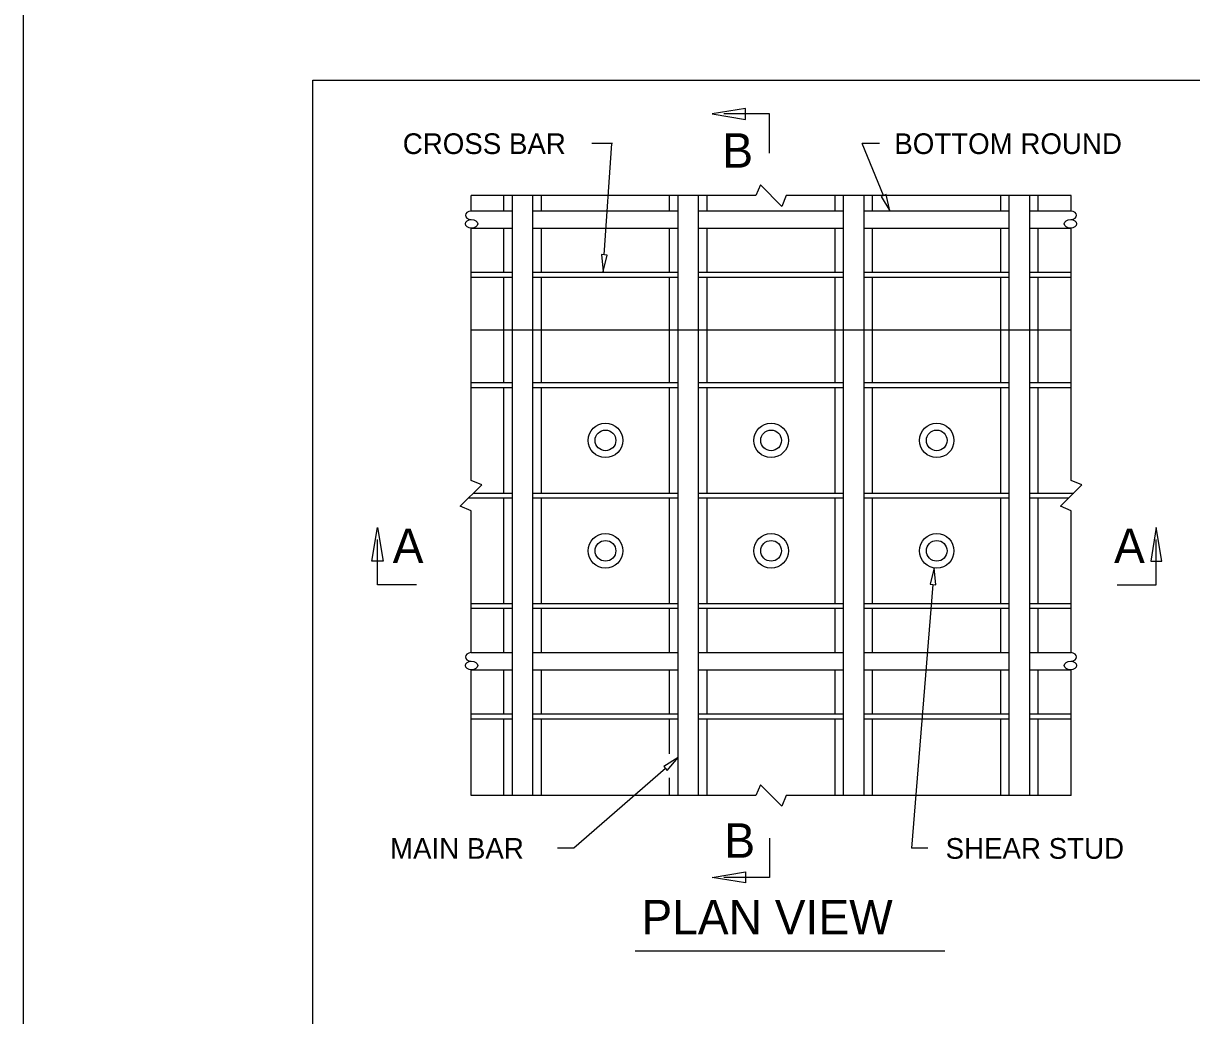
# Model space of a CAD drawing. Extents: x -24512 to -22484, y 4569 to 6351.
# Drawn here: x -24179.8 to -24010.5, y 5605 to 5748.8 of the extents above; entities that cross this region are included whole.
import ezdxf

# ---------------------------------------------------------------- set-up
doc = ezdxf.new("R2010")
doc.units = 0
for name, color, linetype in [('10', 7, 'Continuous'), ('2', 7, 'Continuous'), ('3', 7, 'Continuous'), ('4', 7, 'Continuous'), ('6', 7, 'Continuous'), ('9', 7, 'Continuous'), ('PLT-BNDY', 7, 'Continuous')]:
    doc.layers.add(name, color=color, linetype=linetype)

msp = doc.modelspace()

# ---------------------------------------------------------------- linework, layer by layer
at = {"layer": '10'}
msp.add_line((-24046.26, 5614.39), (-24091.12, 5614.39), dxfattribs=at)
for centre, major_axis, start_param, end_param in [((-24114.81, 5721.02), (0.895, 0), 1.692197, 4.591233), ((-24028.04, 5721.02), (-0.895, 0), 1.691952, 4.590988), ((-24114.81, 5657.02), (0.895, 0), 1.692197, 4.591233), ((-24028.04, 5657.02), (-0.895, 0), 1.691952, 4.590988)]:
    msp.add_ellipse(centre, major_axis=major_axis, ratio=0.699516, start_param=start_param, end_param=end_param, dxfattribs=at)
for centre, major_axis in [((-24114.81, 5719.77), (0.895, 0)), ((-24028.04, 5719.77), (-0.895, 0)), ((-24114.81, 5655.77), (0.895, 0)), ((-24028.04, 5655.77), (-0.895, 0))]:
    msp.add_ellipse(centre, major_axis=major_axis, ratio=0.699516, dxfattribs=at)
at = {"layer": '2'}
for p, q in [((-24137.79, 5740.63), (-23353.75, 5740.63)), ((-24137.79, 5178.04), (-24137.79, 5740.63))]:
    msp.add_line(p, q, dxfattribs=at)
at = {"layer": '3'}
for points in [[(-24075.12, 5734.9), (-24075.12, 5736.52), (-24079.97, 5735.71)], [(-24127.64, 5670.92), (-24129.26, 5670.92), (-24128.45, 5675.77)], [(-24016.41, 5670.92), (-24014.79, 5670.92), (-24015.6, 5675.77)], [(-24075.12, 5625.89), (-24075.12, 5624.27), (-24079.97, 5625.08)]]:
    msp.add_lwpolyline(points, close=True, dxfattribs=at)
for points in [[(-24071.65, 5730.05), (-24071.65, 5735.71), (-24078.25, 5735.71)], [(-24122.79, 5667.45), (-24128.45, 5667.45), (-24128.45, 5674.04)], [(-24021.26, 5667.45), (-24015.6, 5667.45), (-24015.6, 5674.04)], [(-24071.65, 5630.74), (-24071.65, 5625.08), (-24078.25, 5625.08)]]:
    msp.add_lwpolyline(points, dxfattribs=at)
at = {"layer": '4'}
for p, q in [((-24114.88, 5721.65), (-24114.88, 5723.87)), ((-24110.13, 5721.65), (-24110.13, 5723.87)), ((-24108.9, 5636.93), (-24108.9, 5723.87)), ((-24105.93, 5636.93), (-24105.93, 5723.87)), ((-24104.69, 5721.65), (-24104.69, 5723.87)), ((-24086.13, 5721.65), (-24086.13, 5723.87)), ((-24084.9, 5636.93), (-24084.9, 5723.87)), ((-24081.93, 5636.93), (-24081.93, 5723.87)), ((-24080.69, 5721.65), (-24080.69, 5723.87)), ((-24062.13, 5721.65), (-24062.13, 5723.87)), ((-24060.9, 5636.93), (-24060.9, 5723.87)), ((-24057.93, 5636.93), (-24057.93, 5723.87)), ((-24056.7, 5721.65), (-24056.7, 5723.87)), ((-24038.13, 5721.65), (-24038.13, 5723.87)), ((-24036.9, 5636.93), (-24036.9, 5723.87)), ((-24033.93, 5636.93), (-24033.93, 5723.87)), ((-24032.7, 5721.65), (-24032.7, 5723.87)), ((-24027.94, 5721.65), (-24027.94, 5723.87)), ((-24114.88, 5721.65), (-24108.9, 5721.65)), ((-24105.93, 5721.65), (-24084.9, 5721.65)), ((-24081.93, 5721.65), (-24060.9, 5721.65)), ((-24057.93, 5721.65), (-24036.9, 5721.65)), ((-24033.93, 5721.65), (-24027.94, 5721.65)), ((-24114.88, 5719.15), (-24108.9, 5719.15)), ((-24110.13, 5712.77), (-24110.13, 5719.15)), ((-24105.93, 5719.15), (-24084.9, 5719.15)), ((-24104.69, 5712.77), (-24104.69, 5719.15)), ((-24086.13, 5712.77), (-24086.13, 5719.15)), ((-24081.93, 5719.15), (-24060.9, 5719.15)), ((-24080.69, 5712.77), (-24080.69, 5719.15)), ((-24062.13, 5712.77), (-24062.13, 5719.15)), ((-24057.93, 5719.15), (-24036.9, 5719.15)), ((-24056.7, 5712.77), (-24056.7, 5719.15)), ((-24038.13, 5712.77), (-24038.13, 5719.15)), ((-24033.93, 5719.15), (-24027.94, 5719.15)), ((-24032.7, 5712.77), (-24032.7, 5719.15)), ((-24114.88, 5712.77), (-24108.9, 5712.77)), ((-24108.9, 5712.02), (-24114.88, 5712.02)), ((-24110.13, 5696.77), (-24110.13, 5712.02)), ((-24105.93, 5712.77), (-24084.9, 5712.77)), ((-24084.9, 5712.02), (-24105.93, 5712.02)), ((-24104.69, 5696.77), (-24104.69, 5712.02)), ((-24086.13, 5696.77), (-24086.13, 5712.02)), ((-24081.93, 5712.77), (-24060.9, 5712.77)), ((-24060.9, 5712.02), (-24081.93, 5712.02)), ((-24080.69, 5696.77), (-24080.69, 5712.02)), ((-24062.13, 5696.77), (-24062.13, 5712.02)), ((-24057.93, 5712.77), (-24036.9, 5712.77)), ((-24036.9, 5712.02), (-24057.93, 5712.02)), ((-24056.7, 5696.77), (-24056.7, 5712.02)), ((-24038.13, 5696.77), (-24038.13, 5712.02)), ((-24033.93, 5712.77), (-24027.94, 5712.77)), ((-24027.94, 5712.02), (-24033.93, 5712.02)), ((-24032.7, 5696.77), (-24032.7, 5712.02)), ((-24114.88, 5696.77), (-24108.9, 5696.77)), ((-24105.93, 5696.77), (-24084.9, 5696.77)), ((-24081.93, 5696.77), (-24060.9, 5696.77)), ((-24057.93, 5696.77), (-24036.9, 5696.77)), ((-24033.93, 5696.77), (-24027.94, 5696.77)), ((-24108.9, 5696.02), (-24114.88, 5696.02)), ((-24110.13, 5680.77), (-24110.13, 5696.02)), ((-24084.9, 5696.02), (-24105.93, 5696.02)), ((-24104.69, 5680.77), (-24104.69, 5696.02)), ((-24086.13, 5680.77), (-24086.13, 5696.02)), ((-24060.9, 5696.02), (-24081.93, 5696.02)), ((-24080.69, 5680.77), (-24080.69, 5696.02)), ((-24062.13, 5680.77), (-24062.13, 5696.02)), ((-24036.9, 5696.02), (-24057.93, 5696.02)), ((-24056.7, 5680.77), (-24056.7, 5696.02)), ((-24038.13, 5680.77), (-24038.13, 5696.02)), ((-24027.94, 5696.02), (-24033.93, 5696.02)), ((-24032.7, 5680.77), (-24032.7, 5696.02)), ((-24108.9, 5680.02), (-24115.26, 5680.02)), ((-24114.51, 5680.77), (-24108.9, 5680.77)), ((-24110.13, 5664.77), (-24110.13, 5680.02)), ((-24105.93, 5680.77), (-24084.9, 5680.77)), ((-24084.9, 5680.02), (-24105.93, 5680.02)), ((-24104.69, 5664.77), (-24104.69, 5680.02)), ((-24086.13, 5664.77), (-24086.13, 5680.02)), ((-24081.93, 5680.77), (-24060.9, 5680.77)), ((-24060.9, 5680.02), (-24081.93, 5680.02)), ((-24080.69, 5664.77), (-24080.69, 5680.02)), ((-24062.13, 5664.77), (-24062.13, 5680.02)), ((-24057.93, 5680.77), (-24036.9, 5680.77)), ((-24036.9, 5680.02), (-24057.93, 5680.02)), ((-24056.7, 5664.77), (-24056.7, 5680.02)), ((-24038.13, 5664.77), (-24038.13, 5680.02)), ((-24033.93, 5680.77), (-24027.57, 5680.77)), ((-24028.32, 5680.02), (-24033.93, 5680.02)), ((-24032.7, 5664.77), (-24032.7, 5680.02)), ((-24114.88, 5664.77), (-24108.9, 5664.77)), ((-24108.9, 5664.02), (-24114.88, 5664.02)), ((-24110.13, 5657.65), (-24110.13, 5664.02)), ((-24105.93, 5664.77), (-24084.9, 5664.77)), ((-24084.9, 5664.02), (-24105.93, 5664.02)), ((-24104.69, 5657.65), (-24104.69, 5664.02)), ((-24086.13, 5657.65), (-24086.13, 5664.02)), ((-24081.93, 5664.77), (-24060.9, 5664.77)), ((-24060.9, 5664.02), (-24081.93, 5664.02)), ((-24080.69, 5657.65), (-24080.69, 5664.02)), ((-24062.13, 5657.65), (-24062.13, 5664.02)), ((-24057.93, 5664.77), (-24036.9, 5664.77)), ((-24036.9, 5664.02), (-24057.93, 5664.02)), ((-24056.7, 5657.65), (-24056.7, 5664.02)), ((-24038.13, 5657.65), (-24038.13, 5664.02)), ((-24033.93, 5664.77), (-24027.94, 5664.77)), ((-24027.94, 5664.02), (-24033.93, 5664.02)), ((-24032.7, 5657.65), (-24032.7, 5664.02)), ((-24114.88, 5657.65), (-24108.9, 5657.65)), ((-24105.93, 5657.65), (-24084.9, 5657.65)), ((-24081.93, 5657.65), (-24060.9, 5657.65)), ((-24057.93, 5657.65), (-24036.9, 5657.65)), ((-24033.93, 5657.65), (-24027.94, 5657.65)), ((-24114.88, 5655.15), (-24108.9, 5655.15)), ((-24114.88, 5636.93), (-24114.88, 5655.15)), ((-24110.13, 5648.77), (-24110.13, 5655.15)), ((-24105.93, 5655.15), (-24084.9, 5655.15)), ((-24104.69, 5648.77), (-24104.69, 5655.15)), ((-24086.13, 5648.77), (-24086.13, 5655.15)), ((-24081.93, 5655.15), (-24060.9, 5655.15)), ((-24080.69, 5648.77), (-24080.69, 5655.15)), ((-24062.13, 5648.77), (-24062.13, 5655.15)), ((-24057.93, 5655.15), (-24036.9, 5655.15)), ((-24056.7, 5648.77), (-24056.7, 5655.15)), ((-24038.13, 5648.77), (-24038.13, 5655.15)), ((-24033.93, 5655.15), (-24027.94, 5655.15)), ((-24032.7, 5648.77), (-24032.7, 5655.15)), ((-24027.94, 5636.93), (-24027.94, 5655.15)), ((-24114.88, 5648.77), (-24108.9, 5648.77)), ((-24105.93, 5648.77), (-24084.9, 5648.77)), ((-24081.93, 5648.77), (-24060.9, 5648.77)), ((-24057.93, 5648.77), (-24036.9, 5648.77)), ((-24033.93, 5648.77), (-24027.94, 5648.77)), ((-24108.9, 5648.02), (-24114.88, 5648.02)), ((-24110.13, 5636.93), (-24110.13, 5648.02)), ((-24084.9, 5648.02), (-24105.93, 5648.02)), ((-24104.69, 5636.93), (-24104.69, 5648.02)), ((-24086.13, 5642.99), (-24086.13, 5648.02)), ((-24060.9, 5648.02), (-24081.93, 5648.02)), ((-24080.69, 5636.93), (-24080.69, 5648.02)), ((-24062.13, 5636.93), (-24062.13, 5648.02)), ((-24036.9, 5648.02), (-24057.93, 5648.02)), ((-24056.7, 5636.93), (-24056.7, 5648.02)), ((-24038.13, 5636.93), (-24038.13, 5648.02)), ((-24027.94, 5648.02), (-24033.93, 5648.02)), ((-24032.7, 5636.93), (-24032.7, 5648.02)), ((-24086.13, 5636.93), (-24086.13, 5639.49))]:
    msp.add_line(p, q, dxfattribs=at)
for points in [[(-24027.94, 5723.87), (-24069.22, 5723.87), (-24069.86, 5722.32), (-24072.97, 5725.42), (-24073.61, 5723.87), (-24114.88, 5723.87)], [(-24114.88, 5657.65), (-24114.88, 5678.2), (-24116.44, 5678.85), (-24113.33, 5681.95), (-24114.88, 5682.59), (-24114.88, 5719.15)], [(-24027.94, 5657.65), (-24027.94, 5678.2), (-24029.49, 5678.85), (-24026.39, 5681.95), (-24027.94, 5682.59), (-24027.94, 5719.15)], [(-24027.94, 5636.93), (-24069.22, 5636.93), (-24069.86, 5635.38), (-24072.97, 5638.48), (-24073.61, 5636.93), (-24114.88, 5636.93)]]:
    msp.add_lwpolyline(points, dxfattribs=at)
for centre in [(-24095.41, 5688.4), (-24071.41, 5688.4), (-24047.41, 5688.4), (-24095.41, 5672.4), (-24071.41, 5672.4), (-24047.41, 5672.4)]:
    msp.add_circle(centre, 2.5, dxfattribs=at)
at = {"layer": '6'}
msp.add_line((-24027.94, 5704.4), (-24114.88, 5704.4), dxfattribs=at)
for centre in [(-24095.41, 5688.4), (-24071.41, 5688.4), (-24047.41, 5688.4), (-24095.41, 5672.4), (-24071.41, 5672.4), (-24047.41, 5672.4)]:
    msp.add_circle(centre, 1.5, dxfattribs=at)
at = {"layer": '9'}
for p, q in [((-24094.41, 5731.44), (-24097.38, 5731.44)), ((-24094.49, 5731.44), (-24096.81, 5731.44)), ((-24095.58, 5715.29), (-24094.49, 5731.44)), ((-24055.71, 5731.44), (-24058.21, 5731.44)), ((-24055.11, 5723.9), (-24058.21, 5731.44)), ((-24047.96, 5667.51), (-24051.08, 5629.32)), ((-24086.71, 5640.85), (-24099.98, 5629.32)), ((-24099.98, 5629.32), (-24102.37, 5629.32)), ((-24048.72, 5629.32), (-24051.08, 5629.32))]:
    msp.add_line(p, q, dxfattribs=at)
for points in [[(-24054.74, 5724.05), (-24055.48, 5723.75), (-24054.19, 5721.68)], [(-24095.18, 5715.26), (-24095.98, 5715.32), (-24095.75, 5712.9)], [(-24048.36, 5667.55), (-24047.56, 5667.48), (-24047.77, 5669.91)], [(-24086.97, 5641.16), (-24086.45, 5640.55), (-24084.9, 5642.43)]]:
    msp.add_lwpolyline(points, close=True, dxfattribs=at)
at = {"layer": 'PLT-BNDY'}
msp.add_lwpolyline([(-24179.75, 5757.04), (-23338.75, 5757.04), (-23338.75, 5163.04), (-24179.75, 5163.04)], close=True, dxfattribs=at)

# ---------------------------------------------------------------- texts
at = {"layer": '9'}
for s, height, p in [('CROSS BAR', 3, (-24124.78, 5729.9)), ('B', 5, (-24078.48, 5727.92)), ('BOTTOM ROUND', 2.9999, (-24053.56, 5729.9)), ('A', 5, (-24126.24, 5670.63)), ('A', 5, (-24021.72, 5670.63)), ('B', 5, (-24078.19, 5627.91)), ('MAIN BAR', 3, (-24126.63, 5627.77)), ('SHEAR STUD', 3, (-24046.13, 5627.77)), ('PLAN VIEW', 5, (-24090.2, 5616.82))]:
    msp.add_text(s, height=height, dxfattribs=at).set_placement(p)

doc.saveas('drawing.dxf')
